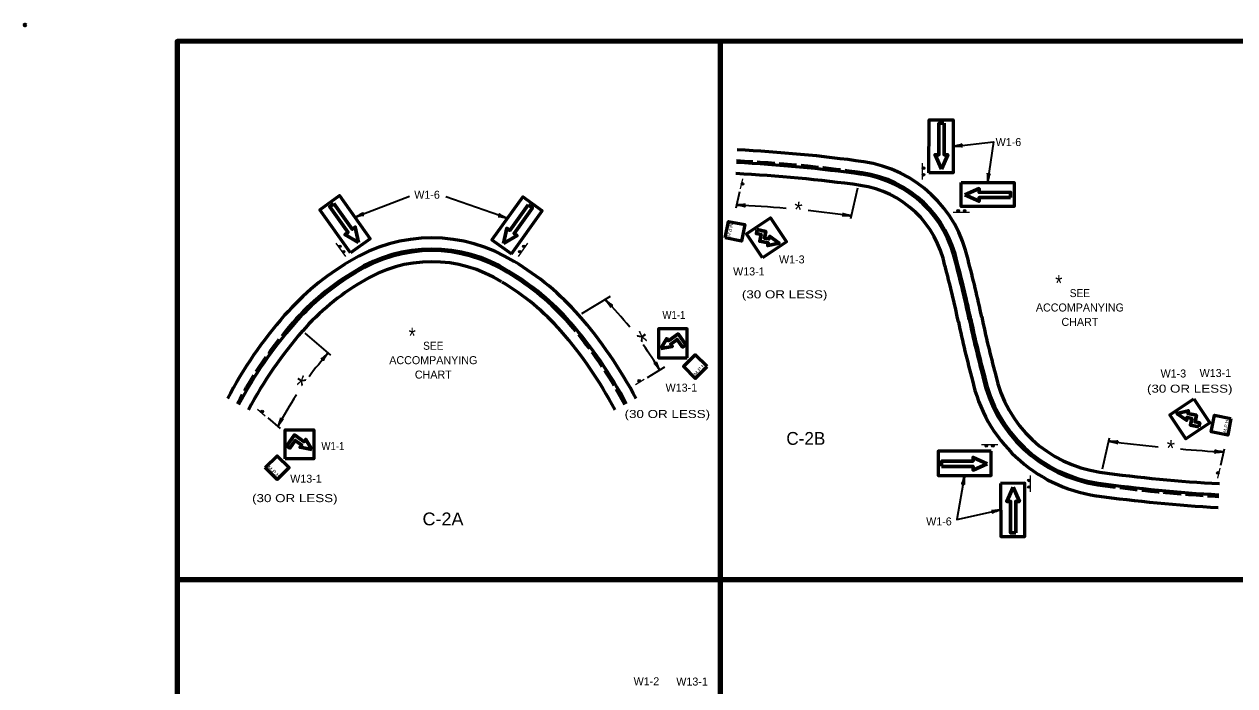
# Model space of a CAD drawing. Extents: x 522 to 1378, y -343 to 201.
# Drawn here: x 522 to 975.7, y -47.3 to 200.6 of the extents above; entities that cross this region are included whole.
import ezdxf
from ezdxf.enums import TextEntityAlignment as Align

# ---------------------------------------------------------------- set-up
doc = ezdxf.new("R2010")
doc.units = 0
doc.header["$LTSCALE"] = 1.1
doc.header["$PDMODE"] = 32
doc.header["$PDSIZE"] = 0.55
doc.linetypes.add('LONG_DASHED', pattern=[7.5, 6, -1.5])
for name, color, linetype, lineweight in [('1', 7, 'Continuous', 53), ('4', 7, 'Continuous', 25), ('61', 7, 'Continuous', 35)]:
    doc.layers.add(name, color=color, linetype=linetype, lineweight=lineweight)

msp = doc.modelspace()

# ---------------------------------------------------------------- hatches: boundary and pattern name
at = {"layer": '4'}
for points in [[(859.035, 147.209, 1), (859.037, 146.225, 1)], [(791.102, 140.29, 1), (791.327, 141.248, 1)], [(859.038, 144.741, 1), (859.04, 143.757, 1)], [(871.53, 130.729, 1), (872.514, 130.732, 1)], [(873.998, 130.732, 1), (874.982, 130.734, 1)], [(640.003, 117.801, 1), (640.583, 117.006, 1)], [(641.455, 115.805, 1), (642.035, 115.01, 1)], [(708.069, 115.805, 1), (707.49, 115.01, 1)], [(709.521, 117.801, 1), (708.941, 117.006, 1)], [(752.956, 67.265, 1), (752.113, 66.758, 1)], [(611.588, 55.201, 1), (610.845, 55.847, 1)], [(882.114, 42.681, 1), (883.098, 42.679, 1)], [(884.582, 42.678, 1), (885.566, 42.676, 1)], [(969.458, 32.957, 1), (969.233, 31.999, 1)], [(898.591, 27.718, 1), (898.589, 26.734, 1)], [(898.594, 30.186, 1), (898.592, 29.202, 1)]]:
    msp.add_hatch(color=256, dxfattribs=at).paths.add_polyline_path(points)

# ---------------------------------------------------------------- linework, layer by layer
at = {"layer": '1', "lineweight": 25}
for p, q in [((858.538, 148.511), (858.544, 142.391)), ((870.229, 130.233), (876.348, 130.239)), ((638.837, 118.563), (642.436, 113.613)), ((710.688, 118.563), (707.088, 113.613)), ((880.812, 43.178), (886.932, 43.172)), ((899.091, 31.487), (899.085, 25.367))]:
    msp.add_line(p, q, dxfattribs=at)
at = {"layer": '1', "lineweight": 35}
for p, q in [((645.903, 128.31), (666.386, 136.15)), ((790.062, 137.835), (788.668, 131.745)), ((834.388, 139.189), (831.75, 127.661)), ((703.06, 127.909), (679.997, 135.956)), ((730.959, 92.175), (741.762, 98.751)), ((627.242, 84.904), (636.829, 76.657)), ((755.574, 68.3), (762.153, 72.305)), ((613.274, 53.135), (617.962, 49.102)), ((926.172, 34.059), (928.81, 45.587)), ((970.499, 35.412), (971.892, 41.503))]:
    msp.add_line(p, q, dxfattribs=at)
at = {"layer": '1', "lineweight": 158}
msp.add_lwpolyline([(1370.988, 194.26), (579.288, 194.16), (579.388, -331.84)], dxfattribs=at)
at = {"layer": '1'}
for points in [[(861.106, 144.915), (861.126, 164.781), (870.181, 164.772), (870.161, 144.906)], [(873.13, 141.35), (892.996, 141.33), (892.987, 132.275), (873.121, 132.295)], [(644.306, 114.965), (632.761, 131.132), (640.13, 136.394), (651.675, 120.227)], [(704.657, 114.563), (716.201, 130.731), (708.832, 135.992), (697.288, 119.825)], [(798.677, 113.138), (792.687, 122.124), (801.673, 128.115), (807.663, 119.128)], [(784.709, 120.59), (785.945, 126.767), (792.122, 125.531), (790.886, 119.354)], [(770.529, 75.65), (770.529, 86.45), (759.729, 86.45), (759.729, 75.65)], [(777.991, 72.315), (773.536, 76.77), (769.081, 72.315), (773.536, 67.861)], [(960.335, 60.292), (966.325, 51.306), (957.338, 45.315), (951.348, 54.302)], [(974.303, 52.84), (973.067, 46.663), (966.889, 47.899), (968.125, 54.076)], [(619.812, 37.82), (619.812, 48.62), (630.612, 48.62), (630.612, 37.82)], [(612.35, 34.486), (616.805, 38.941), (621.26, 34.486), (616.805, 30.031)], [(884.408, 40.61), (864.542, 40.59), (864.551, 31.535), (884.417, 31.555)], [(887.973, 28.586), (887.993, 8.72), (897.048, 8.729), (897.028, 28.595)]]:
    msp.add_lwpolyline(points, close=True, dxfattribs=at)
at = {"layer": '1', "lineweight": 60}
for points in [[(866.744, 163.512), (864.824, 163.514), (864.812, 151.706), (863.397, 151.707), (865.815, 146.377)], [(865.815, 146.377), (868.172, 151.702), (866.781, 151.704), (866.792, 163.512)], [(891.726, 135.712), (891.728, 137.632), (879.92, 137.643), (879.922, 139.059), (874.591, 136.641)], [(874.591, 136.641), (879.917, 134.283), (879.918, 135.675), (891.726, 135.663)], [(638.069, 133.369), (636.507, 132.254), (643.369, 122.644), (642.216, 121.821), (647.285, 118.894)], [(647.285, 118.894), (646.103, 124.597), (644.97, 123.788), (638.108, 133.397)], [(701.677, 118.492), (702.859, 124.195), (703.992, 123.386), (710.854, 132.996)], [(710.893, 132.968), (712.456, 131.852), (705.594, 122.242), (706.746, 121.42), (701.677, 118.492)], [(865.812, 34.972), (865.81, 36.892), (877.618, 36.903), (877.616, 38.319), (882.947, 35.901)], [(882.947, 35.901), (877.621, 33.544), (877.619, 34.935), (865.811, 34.924)], [(893.611, 9.989), (891.692, 9.988), (891.68, 21.796), (890.264, 21.794), (892.683, 27.125)], [(892.683, 27.125), (895.04, 21.799), (893.648, 21.797), (893.66, 9.989)]]:
    msp.add_lwpolyline(points, dxfattribs=at)
at = {"layer": '1', "lineweight": 35}
for points in [[(870.171, 154.839), (885.238, 156.594), (883.063, 141.34)], [(874.484, 31.545), (871.577, 14.985), (887.983, 18.653)]]:
    msp.add_lwpolyline(points, dxfattribs=at)
at = {"layer": '1', "lineweight": 60}
for points in [[(796.726, 123.66), (799.926, 123.019), (799.422, 120.501), (801.164, 120.153), (801.371, 121.188), (804.943, 118.613), (800.665, 117.658), (800.872, 118.694), (797.671, 119.334), (798.175, 121.852), (796.434, 122.201)], [(760.587, 79.088), (764.913, 79.915), (764.302, 80.777), (766.731, 82.497), (768.742, 79.656), (769.957, 80.516), (767.086, 84.571), (763.443, 81.992), (762.832, 82.854)], [(962.286, 49.77), (959.086, 50.411), (959.589, 52.929), (957.848, 53.277), (957.641, 52.242), (954.068, 54.817), (958.347, 55.772), (958.14, 54.736), (961.34, 54.096), (960.837, 51.578), (962.578, 51.229)], [(629.754, 41.259), (625.429, 42.086), (626.039, 42.948), (623.61, 44.667), (621.599, 41.827), (620.385, 42.686), (623.255, 46.741), (626.899, 44.162), (627.509, 45.024)]]:
    msp.add_lwpolyline(points, close=True, dxfattribs=at)
at = {"layer": '1'}
for centre, radius, start, end in [((761.283, -398.143), 552.411, 82.15692, 87.10225), ((761.283, -398.143), 547.646, 82.15692, 87.10226), ((829.834, 102.661), 46.939, 11.99785, 81.63245), ((761.283, -398.143), 543.477, 82.15692, 87.10226), ((829.834, 102.661), 42.174, 11.64996, 81.63245), ((829.834, 102.661), 42.77, 11.6977, 81.63245), ((829.834, 102.661), 38.004, 11.27433, 81.63245), ((674.762, 62.316), 58.24, 57.96316, 122.03684), ((674.762, 62.316), 54.071, 57.96316, 122.14299), ((674.762, 62.316), 53.475, 57.96316, 122.15944), ((695.201, 25.096), 100.664, 120.66054, 138.68723), ((674.762, 62.316), 49.306, 57.96316, 122.28625), ((654.323, 25.096), 100.664, 41.31277, 59.33946), ((499.39, 11.023), 380.843, 11.83276, 15.07823), ((499.39, 11.023), 385.013, 11.83276, 15.07823), ((499.39, 11.023), 385.608, 11.83276, 15.07823), ((499.39, 11.023), 389.778, 11.83276, 15.07823), ((695.201, 25.096), 96.494, 120.66054, 138.68723), ((695.201, 25.096), 95.898, 120.66054, 138.68723), ((654.323, 25.096), 95.898, 41.31277, 59.33946), ((654.323, 25.096), 96.494, 41.31277, 59.33946), ((695.201, 25.096), 91.729, 120.66054, 138.68723), ((654.323, 25.096), 91.729, 41.31277, 59.33946), ((744.782, -17.34), 165.921, 138.98345, 152.07981), ((604.743, -17.34), 165.921, 27.9202, 41.01655), ((1262.38, 170.875), 389.778, 191.83276, 195.07823), ((744.782, -17.34), 161.156, 138.98345, 152.07981), ((604.743, -17.34), 161.752, 27.9202, 41.01655), ((1262.38, 170.875), 398.712, 191.83276, 195.07823), ((1262.38, 170.875), 394.543, 191.83276, 195.07823), ((1262.38, 170.875), 393.947, 191.83276, 195.07823), ((744.782, -17.34), 156.987, 138.98345, 152.07981), ((604.743, -17.34), 156.987, 27.9202, 41.01655), ((931.936, 79.236), 51.704, 191.99785, 261.63245), ((931.936, 79.236), 51.109, 191.99785, 261.63245), ((931.936, 79.236), 46.939, 191.99785, 261.63245), ((931.936, 79.236), 55.874, 191.99785, 261.63245), ((1000.487, 580.041), 552.411, 262.15692, 266.83409), ((1000.487, 580.041), 556.581, 262.15692, 266.83409), ((1000.487, 580.041), 561.346, 262.15692, 266.83409)]:
    msp.add_arc(centre, radius, start, end, dxfattribs=at)
at = {"layer": '1', "linetype": 'LONG_DASHED'}
for centre, radius, start, end in [((761.283, -398.143), 548.242, 82.15692, 87.10226), ((744.782, -17.34), 161.752, 138.98345, 152.07981), ((604.743, -17.34), 161.156, 27.9202, 41.01655), ((1000.487, 580.041), 557.177, 262.15692, 266.83409)]:
    msp.add_arc(centre, radius, start, end, dxfattribs=at)
at = {"layer": '1', "lineweight": 35}
for centre, radius, start, end in [((759.228, -409.75), 543.477, 84.90108, 86.86654), ((759.228, -409.75), 543.477, 82.30307, 84.02449), ((636.519, -3.389), 144.34, 38.82535, 44.27763), ((744.782, -17.34), 144.34, 138.95611, 143.49026), ((636.519, -3.389), 144.34, 30.99169, 35.52584), ((744.782, -17.34), 144.34, 146.78976, 152.24204), ((1001.332, 582.997), 543.477, 262.30307, 264.26854), ((1001.332, 582.997), 543.477, 265.14513, 266.86654)]:
    msp.add_arc(centre, radius, start, end, dxfattribs=at)
at = {"layer": '1', "lineweight": 40}
for centre, major_axis, ratio, start_param, end_param in [((871.433, 155.32), (-2.107, -0.434), 0.122415, 0.8963533, 3.1415927), ((871.433, 155.32), (-2.107, -0.434), 0.122415, 0.8963533, 3.1415927), ((871.536, 154.742), (-2.118, -0.034), 0.07063, 3.1407148, 5.41811), ((871.536, 154.742), (-2.118, -0.034), 0.07063, 3.1407148, 5.41811), ((882.919, 142.683), (-0.117, -2.148), 0.122415, 0.8963533, 3.1415927), ((883.504, 142.635), (-0.506, -2.057), 0.07063, 3.1407148, 5.41811), ((790.264, 132.587), (-2.093, 0.326), 0.07063, 3.1407148, 5.41811), ((790.264, 132.587), (-2.093, 0.326), 0.07063, 3.1407148, 5.41811), ((790.261, 133.174), (-2.15, -0.07), 0.122415, 0.8963533, 3.1415927), ((790.261, 133.174), (-2.15, -0.07), 0.122415, 0.8963533, 3.1415927), ((647.007, 129.088), (-1.934, -0.941), 0.122415, 0.8963533, 3.1415927), ((647.007, 129.088), (-1.934, -0.941), 0.122415, 0.8963533, 3.1415927), ((647.249, 128.554), (-2.044, -0.557), 0.07063, 3.1407148, 5.41811), ((647.249, 128.554), (-2.044, -0.557), 0.07063, 3.1407148, 5.41811), ((701.714, 128.027), (2.085, -0.529), 0.122415, 0.8963533, 3.1415927), ((701.874, 128.591), (1.921, -0.893), 0.07063, 3.1407148, 5.41811), ((830.676, 128.677), (2.149, -0.101), 0.122415, 0.8963533, 3.1415927), ((830.719, 129.262), (2.061, -0.491), 0.07063, 3.1407148, 5.41811), ((740.618, 96.24), (-1.321, 1.656), 0.07063, 3.1407148, 5.41811), ((741.012, 96.674), (-1.63, 1.403), 0.122415, 0.8963533, 3.1415927), ((634.845, 76.592), (1.543, 1.451), 0.07063, 3.1407148, 5.41811), ((634.845, 76.592), (1.543, 1.451), 0.07063, 3.1407148, 5.41811), ((635.31, 76.234), (1.266, 1.739), 0.122415, 0.8963533, 3.1415927), ((635.31, 76.234), (1.266, 1.739), 0.122415, 0.8963533, 3.1415927), ((759.294, 71.886), (1.264, -1.74), 0.122415, 0.8963533, 3.1415927), ((759.778, 72.217), (0.905, -1.915), 0.07063, 3.1407148, 5.41811), ((617.369, 51.198), (-0.832, -1.984), 0.122415, 0.8963533, 3.1415927), ((617.903, 50.956), (-1.168, -1.767), 0.07063, 3.1407148, 5.41811), ((929.841, 43.986), (-2.061, 0.491), 0.07063, 3.1407148, 5.41811), ((929.885, 44.57), (-2.149, 0.101), 0.122415, 0.8963533, 3.1415927), ((970.296, 40.66), (2.093, -0.326), 0.07063, 3.1407148, 5.41811), ((970.299, 40.074), (2.15, 0.07), 0.122415, 0.8963533, 3.1415927), ((874.001, 30.265), (0.572, 2.04), 0.07063, 3.1407148, 5.41811), ((874.001, 30.265), (0.572, 2.04), 0.07063, 3.1407148, 5.41811), ((874.584, 30.198), (0.186, 2.143), 0.122415, 0.8963533, 3.1415927), ((874.584, 30.198), (0.186, 2.143), 0.122415, 0.8963533, 3.1415927), ((886.616, 18.607), (2.103, 0.254), 0.07063, 3.1407148, 5.41811), ((886.778, 18.044), (2.05, 0.65), 0.122415, 0.8963533, 3.1415927)]:
    msp.add_ellipse(centre, major_axis=major_axis, ratio=ratio, start_param=start_param, end_param=end_param, dxfattribs=at)
at = {"layer": '1'}
msp.add_point((522.288, 200.36), dxfattribs=at)
at = {"layer": '4'}
for p, q in [((791.186, 142.748), (790.309, 139.01)), ((751.137, 65.611), (754.428, 67.59)), ((609.453, 56.422), (612.35, 53.902)), ((969.375, 30.499), (970.251, 34.238))]:
    msp.add_line(p, q, dxfattribs=at)
for centre in [(859.036, 146.717), (791.215, 140.769), (859.039, 144.249), (872.022, 130.73), (874.49, 130.733), (640.293, 117.403), (641.745, 115.407), (707.779, 115.407), (709.231, 117.403), (752.535, 67.011), (611.217, 55.524), (882.606, 42.68), (885.074, 42.677), (969.346, 32.478), (898.59, 27.226), (898.593, 29.694)]:
    msp.add_circle(centre, 0.492, dxfattribs=at)
at = {"layer": '61', "lineweight": 158}
for p, q in [((782.822, 194.186), (782.822, -167.2)), ((1370.988, -7.57), (579.326, -7.57))]:
    msp.add_line(p, q, dxfattribs=at)

# ---------------------------------------------------------------- texts
at = {"layer": '1'}
for s, height, p in [('W1-6', 3, (890.891, 154.971)), ('W1-6', 3, (672.997, 135.234)), ('W1-3', 3, (809.697, 111.004)), ('W13-1', 3, (793.612, 106.499)), ('ACCOMPANYING', 3, (917.679, 92.983)), ('CHART', 3, (917.679, 87.583)), ('ACCOMPANYING', 3, (675.336, 73.246)), ('CHART', 3, (675.336, 67.846)), ('W1-3', 3, (952.709, 68.25)), ('W13-1', 3, (968.459, 68.433)), ('W13-1', 3, (768.305, 62.949)), ('C-2B', 4.8, (814.96, 43.026)), ('W13-1', 3, (627.618, 28.838)), ('W1-6', 3, (864.852, 12.828)), ('W1-2', 3, (755.214, -47.084)), ('W13-1', 3, (772.322, -47.183))]:
    msp.add_text(s, height=height, dxfattribs=at).set_placement(p, align=Align.CENTER)
for p in [(810.234, 128.315), (949.76, 38.96)]:
    msp.add_text('*', height=6, rotation=354.585, dxfattribs=at).set_placement(p)
for s, height, rotation, width, p in [('M.P.H.', 1.2, 258.499, 1.1, (786.493, 125.983)), ('*', 6, 307.635, 1.7, (748.448, 82.917)), ('M.P.H.', 1.2, 47.275, 1.25, (773.612, 68.841)), ('*', 6, 55.599, 1.55, (628.162, 62.515)), ('M.P.H.', 1.2, 78.499, 1.1, (972.518, 47.447)), ('M.P.H.', 1.2, 317.275, 1.25, (613.146, 34.482))]:
    msp.add_text(s, height=height, rotation=rotation, dxfattribs=dict(at, width=width)).set_placement(p)
at = {"layer": '1', "width": 0.85}
for p in [(908.437, 100.616), (666.094, 80.879)]:
    msp.add_text('*', height=6, dxfattribs=at).set_placement(p)
at = {"layer": '1'}
for s, height, width, p in [('(30 OR LESS)', 3, 1.25, (807.016, 97.917)), ('SEE', 3, 0.95, (917.679, 98.383)), ('W1-1', 3, 0.9, (765.517, 90.194)), ('SEE', 3, 0.95, (675.336, 78.646)), ('(30 OR LESS)', 3, 1.25, (958.846, 62.579)), ('(30 OR LESS)', 3, 1.25, (763.051, 53.08)), ('W1-1', 3, 0.9, (637.697, 41.066)), ('(30 OR LESS)', 3, 1.25, (623.436, 21.544)), ('C-2A', 4.8, 1.05, (678.972, 12.857))]:
    msp.add_text(s, height=height, dxfattribs=dict(at, width=width)).set_placement(p, align=Align.CENTER)

doc.saveas('drawing.dxf')
